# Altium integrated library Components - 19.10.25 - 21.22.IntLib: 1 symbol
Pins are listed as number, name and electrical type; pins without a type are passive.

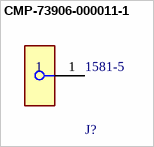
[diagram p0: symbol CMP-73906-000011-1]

## CMP-73906-000011-1
designator J?, comment 1581-5
CONN BANANA JACK TURRET GREEN; Body Material: PC; Number of Contacts: 1; Max Current Rating: 15A; Voltage Rating (AC): 30V; Insulation: Mating End Insulated; Voltage Rating: 2.5kV; Voltage Rating (DC): 60V; Gender: Female
footprint FP-1581-5-MFG
pins: 1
